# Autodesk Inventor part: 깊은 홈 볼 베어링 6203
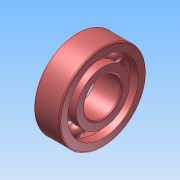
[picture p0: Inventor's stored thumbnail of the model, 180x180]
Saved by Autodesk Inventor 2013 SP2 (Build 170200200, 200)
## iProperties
Created: 2025-05
Part Number: 깊은 홈 볼 베어링 6203
Material: Generic
Document SubType Name: Modeling
Designer: a
Density: 1 g/cm^3
Author: a
변환 표준: STEP AP214IS
전처리기: Build: 200, Release: 2013 SP2 Update 6 - Date: Thu 07/17/2014
전송 단위: 밀리미터
불확실성: 0.01
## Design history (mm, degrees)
node "깊은 홈 볼 베어링 62031"
body "Solid1"
node "Solid1_1"
node "Solid1_2"
node "Solid1_3"
node "Solid1_4"
node "Solid1_5"
node "Solid1_6"
node "Solid1_7"
node "Solid1_8"
node "기준1"
node "기준2"
node "기준3"
node "기준4"
node "기준5"
node "기준6"
node "기준7"
node "기준8"
node "기준9"
